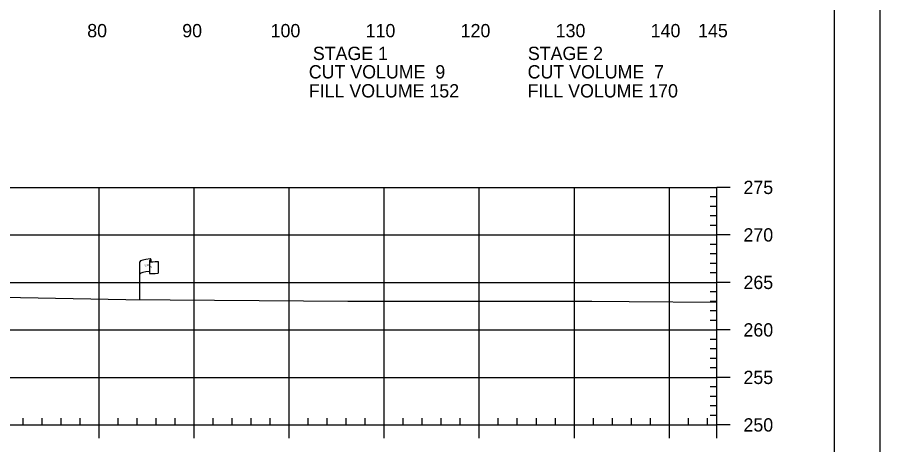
# Model space of a CAD drawing. Extents: x 1365647 to 1367999, y 387113 to 400173.
# Drawn here: x 1365966.3 to 1366057, y 388334 to 388379 of the extents above; entities that cross this region are included whole.
import ezdxf

# ---------------------------------------------------------------- set-up
doc = ezdxf.new("R2010")
doc.units = 0
for name, color, linetype in [('E_Existing ROW', 7, 'Continuous'), ('R_Axis', 7, 'Continuous'), ('R_Axis Annot', 7, 'Continuous'), ('R_Border', 7, 'Continuous'), ('R_Exist Surface', 7, 'Continuous'), ('R_Grid', 7, 'Continuous'), ('R_No Plot', 7, 'Continuous')]:
    doc.layers.add(name, color=color, linetype=linetype)

msp = doc.modelspace()

# ---------------------------------------------------------------- linework, layer by layer
at = {"layer": 'E_Existing ROW'}
for p, q in [((1365980.336, 388353.475), (1365980.336, 388353.235)), ((1365979.173, 388349.274), (1365979.173, 388353.224)), ((1365980.168, 388353.319), (1365980.168, 388353.305)), ((1365980.168, 388353.305), (1365980.168, 388352.079)), ((1365981.104, 388353.281), (1365981.104, 388352.041))]:
    msp.add_line(p, q, dxfattribs=at)
for centre, radius, start, end in [((1365980.246, 388353.319), 0.078, 88.6458, 274.28284), ((1365980.257, 388353.475), 0.0783, 263.07118, 93.95638), ((1365980.247, 388352.079), 0.0783, 180, 273.95638)]:
    msp.add_arc(centre, radius, start, end, dxfattribs=at)
for centre, major_axis, ratio, start_param, end_param in [((1365980.755, 388353.268), (-1.582, -0.043), 0.19887, 5.030368, 6.283185), ((1365981.462, 388353.383), (-1.227, -0.134), 0.052933, 0.159456, 1.268315), ((1365980.75, 388351.95), (-1.582, -0.043), 0.19887, 5.083035, 6.194897), ((1365981.462, 388352.143), (-1.227, -0.134), 0.052933, 0.159456, 1.268315)]:
    msp.add_ellipse(centre, major_axis=major_axis, ratio=ratio, start_param=start_param, end_param=end_param, dxfattribs=at)
at = {"layer": 'R_Axis'}
for p, q in [((1366039.888, 388336.069), (1366039.888, 388361.069)), ((1366041.288, 388361.069), (1366039.888, 388361.069)), ((1366039.888, 388360.069), (1366039.188, 388360.069)), ((1366039.888, 388359.069), (1366039.188, 388359.069)), ((1366039.888, 388358.069), (1366039.188, 388358.069)), ((1366039.888, 388357.069), (1366039.188, 388357.069)), ((1366041.288, 388356.069), (1366039.888, 388356.069)), ((1366039.888, 388355.069), (1366039.188, 388355.069)), ((1366039.888, 388354.069), (1366039.188, 388354.069)), ((1366039.888, 388353.069), (1366039.188, 388353.069)), ((1366039.888, 388352.069), (1366039.188, 388352.069)), ((1366041.288, 388351.069), (1366039.888, 388351.069)), ((1366039.888, 388350.069), (1366039.188, 388350.069)), ((1366039.888, 388349.069), (1366039.188, 388349.069)), ((1366039.888, 388348.069), (1366039.188, 388348.069)), ((1366039.888, 388347.069), (1366039.188, 388347.069)), ((1366041.288, 388346.069), (1366039.888, 388346.069)), ((1366039.888, 388345.069), (1366039.188, 388345.069)), ((1366039.888, 388344.069), (1366039.188, 388344.069)), ((1366039.888, 388343.069), (1366039.188, 388343.069)), ((1366039.888, 388342.069), (1366039.188, 388342.069)), ((1366041.288, 388341.069), (1366039.888, 388341.069)), ((1366039.888, 388340.069), (1366039.188, 388340.069)), ((1366039.888, 388339.069), (1366039.188, 388339.069)), ((1366039.888, 388338.069), (1366039.188, 388338.069)), ((1366039.888, 388337.069), (1366039.188, 388337.069)), ((1365966.888, 388336.069), (1365966.888, 388336.769)), ((1365968.888, 388336.069), (1365968.888, 388336.769)), ((1365970.888, 388336.069), (1365970.888, 388336.769)), ((1365972.888, 388336.069), (1365972.888, 388336.769)), ((1365976.888, 388336.069), (1365976.888, 388336.769)), ((1365978.888, 388336.069), (1365978.888, 388336.769)), ((1365980.888, 388336.069), (1365980.888, 388336.769)), ((1365982.888, 388336.069), (1365982.888, 388336.769)), ((1365986.888, 388336.069), (1365986.888, 388336.769)), ((1365988.888, 388336.069), (1365988.888, 388336.769)), ((1365990.888, 388336.069), (1365990.888, 388336.769)), ((1365992.888, 388336.069), (1365992.888, 388336.769)), ((1365996.888, 388336.069), (1365996.888, 388336.769)), ((1365998.888, 388336.069), (1365998.888, 388336.769)), ((1366000.888, 388336.069), (1366000.888, 388336.769)), ((1366002.888, 388336.069), (1366002.888, 388336.769)), ((1366006.888, 388336.069), (1366006.888, 388336.769)), ((1366008.888, 388336.069), (1366008.888, 388336.769)), ((1366010.888, 388336.069), (1366010.888, 388336.769)), ((1366012.888, 388336.069), (1366012.888, 388336.769)), ((1366016.888, 388336.069), (1366016.888, 388336.769)), ((1366018.888, 388336.069), (1366018.888, 388336.769)), ((1366020.888, 388336.069), (1366020.888, 388336.769)), ((1366022.888, 388336.069), (1366022.888, 388336.769)), ((1366026.888, 388336.069), (1366026.888, 388336.769)), ((1366028.888, 388336.069), (1366028.888, 388336.769)), ((1366030.888, 388336.069), (1366030.888, 388336.769)), ((1366032.888, 388336.069), (1366032.888, 388336.769)), ((1366036.888, 388336.069), (1366036.888, 388336.769)), ((1366038.888, 388336.069), (1366038.888, 388336.769)), ((1365749.888, 388336.069), (1366039.888, 388336.069)), ((1365974.888, 388334.669), (1365974.888, 388336.069)), ((1365984.888, 388334.669), (1365984.888, 388336.069)), ((1365994.888, 388334.669), (1365994.888, 388336.069)), ((1366004.888, 388334.669), (1366004.888, 388336.069)), ((1366014.888, 388334.669), (1366014.888, 388336.069)), ((1366024.888, 388334.669), (1366024.888, 388336.069)), ((1366034.888, 388334.669), (1366034.888, 388336.069)), ((1366039.888, 388334.669), (1366039.888, 388336.069)), ((1366041.288, 388336.069), (1366039.888, 388336.069))]:
    msp.add_line(p, q, dxfattribs=at)
at = {"layer": 'R_Border'}
msp.add_line((1366052.275, 388230.069), (1366052.275, 388435.529), dxfattribs=at)
at = {"layer": 'R_Exist Surface'}
msp.add_lwpolyline([(1365952.153, 388349.716), (1365966.596, 388349.464), (1365977.688, 388349.285), (1366001.044, 388349.105), (1366002.125, 388349.098), (1366002.8, 388349.097), (1366026.716, 388349.11), (1366030.659, 388349.074), (1366039.888, 388348.977)], dxfattribs=at)
at = {"layer": 'R_Grid'}
for p, q in [((1365749.888, 388361.069), (1366039.888, 388361.069)), ((1365974.888, 388336.069), (1365974.888, 388361.069)), ((1365984.888, 388336.069), (1365984.888, 388361.069)), ((1365994.888, 388336.069), (1365994.888, 388361.069)), ((1366004.888, 388336.069), (1366004.888, 388361.069)), ((1366014.888, 388336.069), (1366014.888, 388361.069)), ((1366024.888, 388336.069), (1366024.888, 388361.069)), ((1366034.888, 388336.069), (1366034.888, 388361.069)), ((1366039.888, 388336.069), (1366039.888, 388361.069)), ((1365749.888, 388356.069), (1366039.888, 388356.069)), ((1365749.888, 388351.069), (1366039.888, 388351.069)), ((1365749.888, 388346.069), (1366039.888, 388346.069)), ((1365749.888, 388341.069), (1366039.888, 388341.069)), ((1365749.888, 388336.069), (1366039.888, 388336.069))]:
    msp.add_line(p, q, dxfattribs=at)
at = {"layer": 'R_No Plot'}
msp.add_lwpolyline([(1365723.687, 388439.423), (1366057.027, 388439.423), (1366057.027, 388226.086), (1365723.687, 388226.086)], close=True, dxfattribs=at)

# ---------------------------------------------------------------- texts
at = {"layer": 'E_Existing ROW'}
for s, height, rotation, p in [('R ', 0.2, 9.98841, (1365979.692, 388352.726)), (' O', 0.2, 9.98841, (1365979.838, 388352.771)), ('W', 0.2, 351.17882, (1365980.168, 388352.602)), ('DWB 11-9-07', 0.001, 90, (1365980.336, 388353.235)), ('DWB 11-9-07', 0.001, 5.07169, (1365981.093, 388352.041)), ('DWB 11-9-07', 0.001, 90, (1365979.172, 388349.274))]:
    msp.add_text(s, height=height, rotation=rotation, dxfattribs=at).set_placement(p)
at = {"layer": 'R_Axis Annot'}
for s, p in [('80', (1365973.627, 388376.869)), ('90', (1365983.627, 388376.869)), ('100', (1365992.927, 388376.869)), ('110', (1366002.927, 388376.869)), ('120', (1366012.927, 388376.869)), ('130', (1366022.927, 388376.869)), ('140', (1366032.927, 388376.869)), ('145', (1366037.914, 388376.869)), ('STAGE 1', (1365997.371, 388374.476)), ('STAGE 2', (1366020, 388374.476)), ('CUT VOLUME  9', (1365996.946, 388372.535)), ('CUT VOLUME  7', (1366019.972, 388372.535)), ('FILL VOLUME 152', (1365996.946, 388370.535)), ('FILL VOLUME 170', (1366019.972, 388370.535)), ('275', (1366042.688, 388360.369)), ('270', (1366042.688, 388355.369)), ('265', (1366042.688, 388350.369)), ('260', (1366042.688, 388345.369)), ('255', (1366042.688, 388340.369)), ('250', (1366042.688, 388335.369))]:
    msp.add_text(s, height=1.4, dxfattribs=at).set_placement(p)

doc.saveas('drawing.dxf')
